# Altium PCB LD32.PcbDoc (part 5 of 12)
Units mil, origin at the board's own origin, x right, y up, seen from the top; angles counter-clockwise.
Board outline 7007.87 x 4368.85 mil, 12 copper layers (Top Layer, Int1 (GND), Int2 (AVDD), Int3 (DVDD), Int4 (GND), Int5 (ST), Int6 (SB), Int8 (AGND), Int7 (AVCC), Int9 (VCCA), Int10 (GND), Bottom Layer), stack 60.136 mil thick; 1165 components, 667 nets, 3910 pads, 2570 vias.
Unrouted connection lines stored in the file: 14.
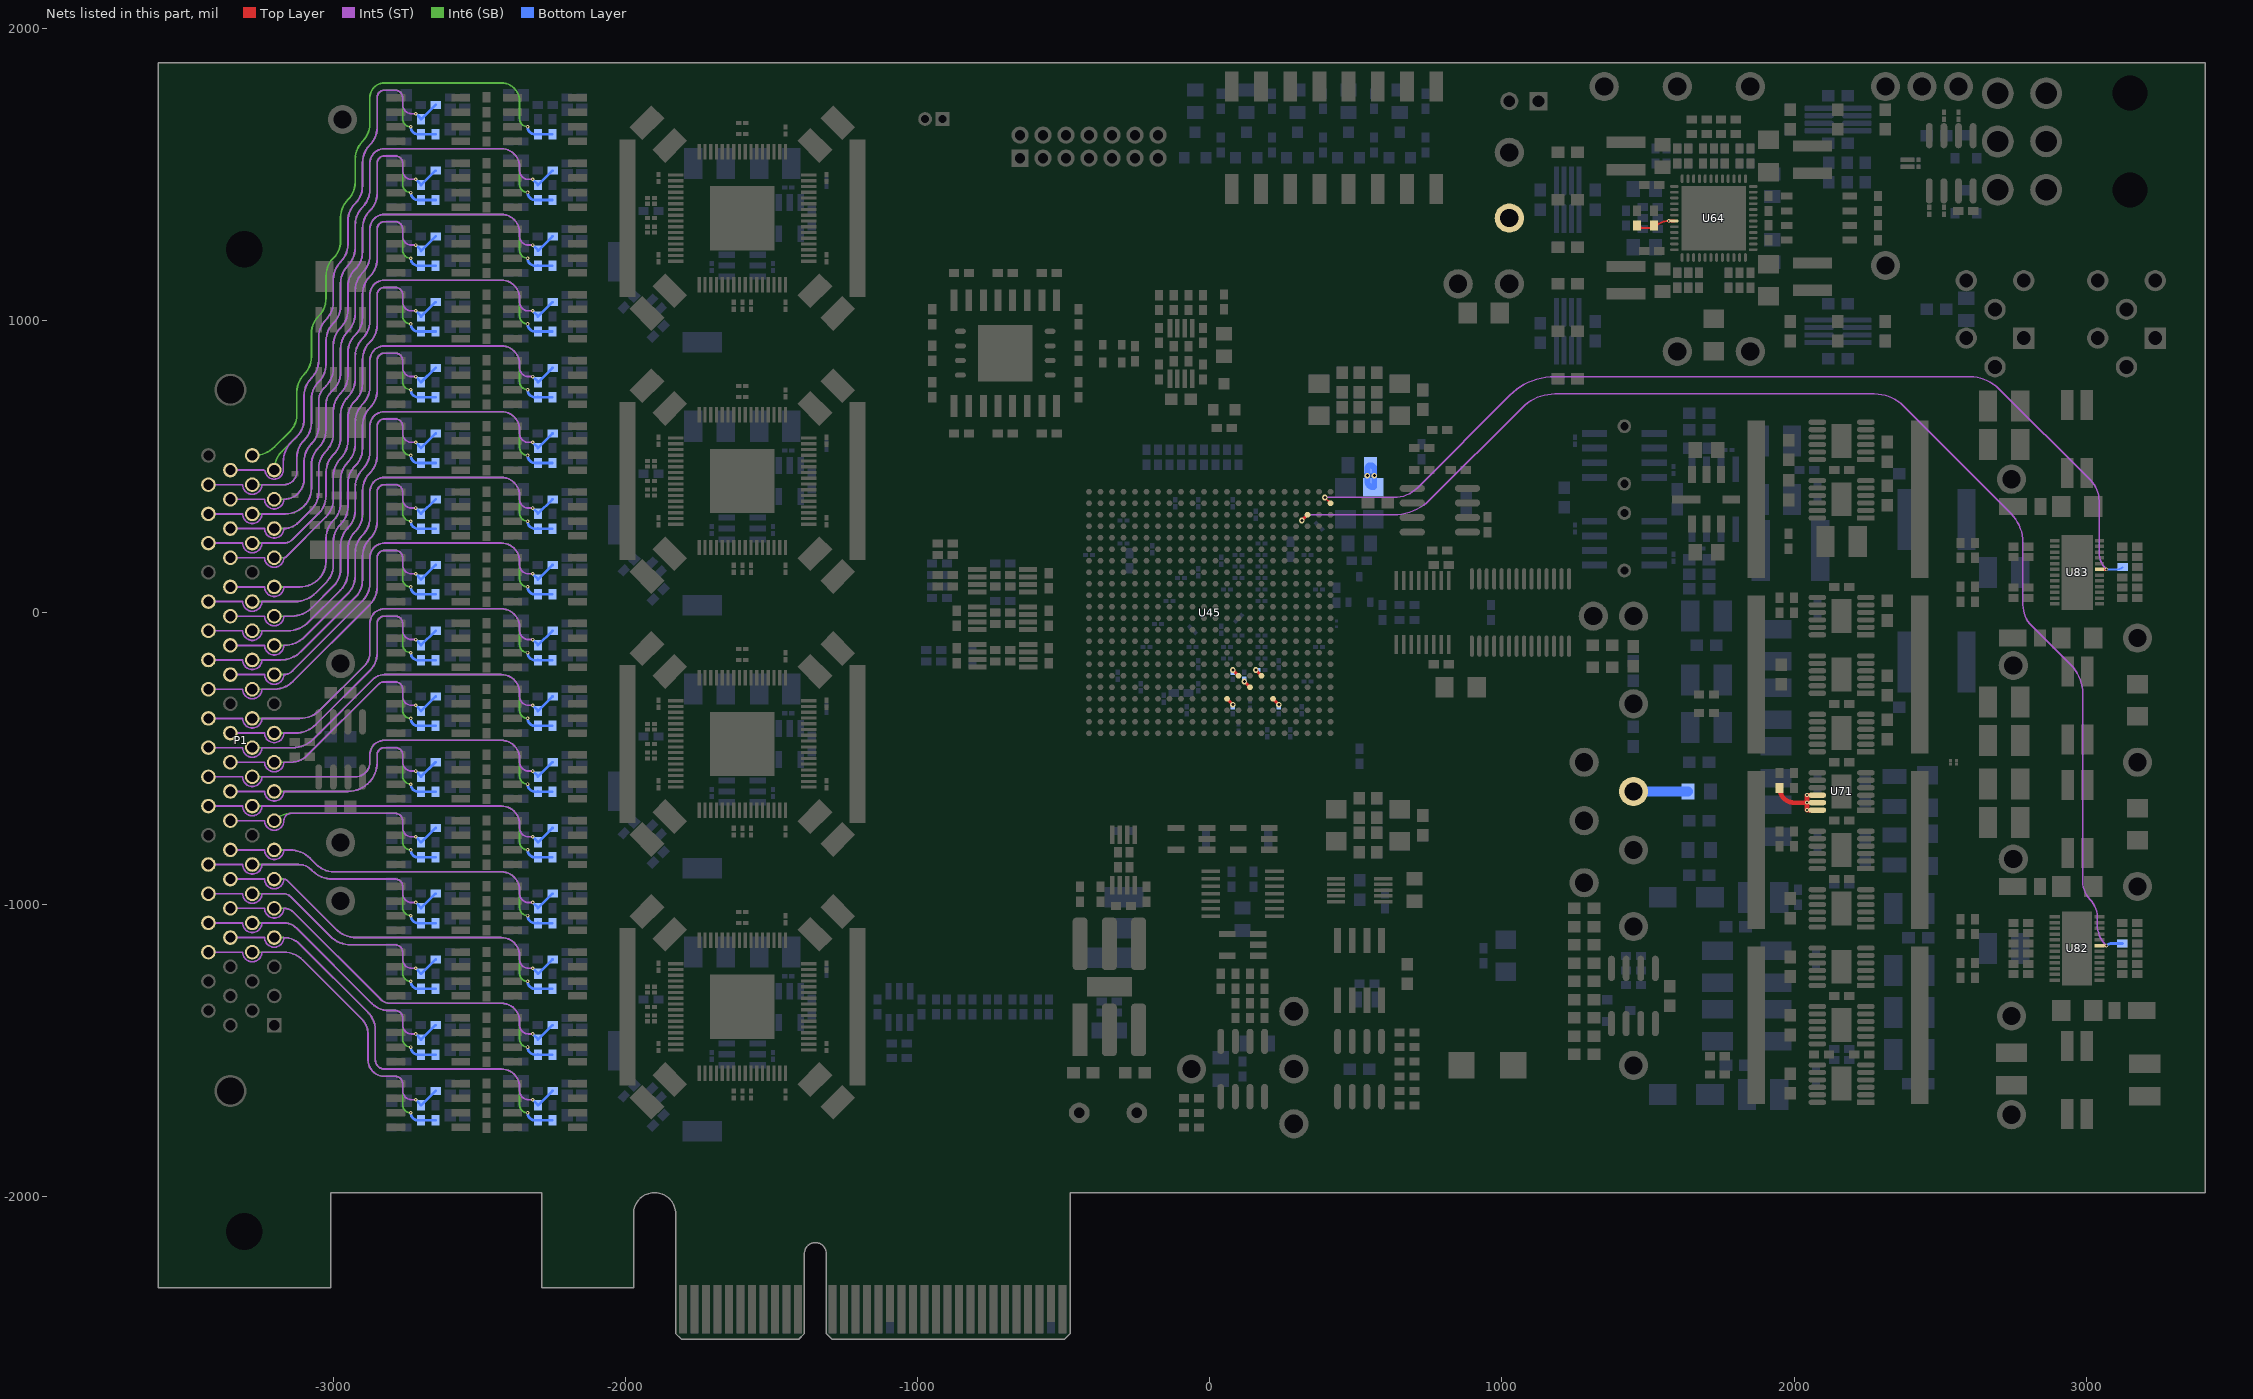
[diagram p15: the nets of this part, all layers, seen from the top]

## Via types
v1: diameter 12, hole 6, Top Layer to Bottom Layer, tented both sides, 1500 vias
v2: diameter 19, hole 10, Top Layer to Bottom Layer, tented both sides, 404 vias
v3: diameter 20, hole 10, Top Layer to Bottom Layer, tented both sides, 337 vias
v4: diameter 14, hole 7, Top Layer to Bottom Layer, tented both sides, 212 vias
v5: diameter 30, hole 15, Top Layer to Bottom Layer, tented both sides, 37 vias
v6: diameter 19.68, hole 7.87, Top Layer to Bottom Layer, 25 vias
v7: diameter 40, hole 20, Top Layer to Bottom Layer, tented both sides, 16 vias
v8: diameter 19.02, hole 10, Top Layer to Bottom Layer, tented both sides, 10 vias
v9: diameter 40, hole 20, Top Layer to Bottom Layer, 9 vias
v10: diameter 60, hole 40, Top Layer to Bottom Layer, 5 vias
v11: diameter 25, hole 13, Top Layer to Bottom Layer, 4 vias
v12: diameter 50, hole 25, Top Layer to Bottom Layer, tented both sides, 4 vias
v13: diameter 35, hole 20, Top Layer to Bottom Layer, 2 vias
v14: diameter 50, hole 25, Top Layer to Bottom Layer, 2 vias
v15: diameter 63, hole 45, Top Layer to Bottom Layer, 1 vias
v16: diameter 14.02, hole 7.01, Top Layer to Bottom Layer, tented both sides, 1 vias
v17: diameter 60, hole 40, Top Layer to Bottom Layer, tented both sides, 1 vias

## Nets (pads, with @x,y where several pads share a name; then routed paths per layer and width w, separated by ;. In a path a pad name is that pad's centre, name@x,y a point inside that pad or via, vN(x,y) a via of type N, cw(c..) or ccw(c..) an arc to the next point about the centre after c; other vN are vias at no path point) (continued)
ANALOG1.A1_P: C351C.2 P1.79 R367C.2 | length 2547
  Int6 (SB) w6: P1.79@-3277.3,537.5 -3272.05,537.5 ccw(c-3272.05,637.5) -3201.34,566.79 -3147.53,620.6 ccw(c-3201.93,675) -3125,675 -3125,754.29 cw(c-3039.64,754.29) -3100,814.64 ccw(c-3160.36,875) -3075,875 -3075,954.29 cw(c-2989.64,954.29) -3050,1014.64 ccw(c-3110.36,1075) -3025,1075 -3025,1152.14 cw(c-2939.64,1152.14) -3000,1212.5 ccw(c-3060.36,1272.86) -2975,1272.86 -2975,1352.14 cw(c-2889.64,1352.14) -2950,1412.5 ccw(c-3010.36,1472.86) -2925,1472.86 -2925,1552.14 cw(c-2839.64,1552.14) -2900,1612.5 ccw(c-2960.36,1672.86) -2875,1672.86 -2875,1762.5 cw(c-2825,1762.5) -2825,1812.5 -2425,1812.5 ; v1(-2335,1662.75) cw(c-2335,1690.25) -2362.5,1690.25 -2362.5,1750 ; -2425,1812.5 cw(c-2425,1750) -2362.5,1750 ; -2425,1812.5 cw(c-2425,1750) -2362.5,1750 ; -2425,1812.5 cw(c-2425,1750) -2362.5,1750 ; -2425,1812.5 cw(c-2425,1750) -2362.5,1750 ; -2425,1812.5 cw(c-2425,1750) -2362.5,1750
  Bottom Layer w9: v1(-2335,1662.75) ccw(c-2309.15,1662.75) -2309.15,1636.91 C351C.2@-2300,1636.91 ; C351C.2@-2300,1637.5 -2299.41,1636.91 R367C.2@-2250,1636.91
ANALOG1.A2_N: C351D.1 P1.68 R351D.2 | length 2391.9
  Int5 (ST) w6: P1.68@-3427.3,237.5 -3310.3,237.5 ccw(c-3277.3,237.5) -3244.3,237.5 -3169.3,237.5 ccw(c-3169.3,278.92) -3140.01,249.63 -3050,339.64 ccw(c-3110.36,400) -3025,400 -3025,479.29 cw(c-2939.64,479.29) -3000,539.64 ccw(c-3060.36,600) -2975,600 -2975,677.14 cw(c-2889.64,677.14) -2950,737.5 ccw(c-3010.36,797.86) -2925,797.86 -2925,877.14 cw(c-2839.64,877.14) -2900,937.5 ccw(c-2960.36,997.86) -2875,997.86 -2875,1087.5 cw(c-2825,1087.5) -2825,1137.5 -2425,1137.5 ; v1(-2317.5,1032.5) -2332.5,1032.5 cw(c-2332.5,1062.5) -2362.5,1062.5 -2362.5,1075 ; -2425,1137.5 cw(c-2425,1075) -2362.5,1075 ; -2425,1137.5 cw(c-2425,1075) -2362.5,1075 ; -2425,1137.5 cw(c-2425,1075) -2362.5,1075 ; -2425,1137.5 cw(c-2425,1075) -2362.5,1075 ; -2425,1137.5 cw(c-2425,1075) -2362.5,1075
  Bottom Layer w9: v1(-2317.5,1032.5) -2300,1015 C351D.1@-2300,1013.09 -2250.59,1062.5 R351D.2@-2249.41,1062.5
ANALOG1.A2_P: C351D.2 P1.67 R367D.2 | length 2234.8
  Int6 (SB) w6: P1.67@-3277.3,237.5 -3169.3,237.5 ccw(c-3169.3,278.92) -3140.01,249.63 -3050,339.64 ccw(c-3110.36,400) -3025,400 -3025,479.29 cw(c-2939.64,479.29) -3000,539.64 ccw(c-3060.36,600) -2975,600 -2975,677.14 cw(c-2889.64,677.14) -2950,737.5 ccw(c-3010.36,797.86) -2925,797.86 -2925,877.14 cw(c-2839.64,877.14) -2900,937.5 ccw(c-2960.36,997.86) -2875,997.86 -2875,1087.5 cw(c-2825,1087.5) -2825,1137.5 -2425,1137.5 ; v1(-2335,987.75) cw(c-2335,1015.25) -2362.5,1015.25 -2362.5,1075 ; -2425,1137.5 cw(c-2425,1075) -2362.5,1075 ; -2425,1137.5 cw(c-2425,1075) -2362.5,1075 ; -2425,1137.5 cw(c-2425,1075) -2362.5,1075 ; -2425,1137.5 cw(c-2425,1075) -2362.5,1075 ; -2425,1137.5 cw(c-2425,1075) -2362.5,1075
  Bottom Layer w9: v1(-2335,987.75) ccw(c-2309.15,987.75) -2309.15,961.91 C351D.2@-2300,961.91 ; C351D.2@-2300,962.5 -2299.41,961.91 R367D.2@-2250,961.91
ANALOG1.A3_N: C431C.1 P1.78 R415C.2 | length 1876.3
  Int5 (ST) w6: P1.78@-3352.3,487.5 -3238.78,487.5 cw(c-3238.81,481.5) -3232.9,482.5 ccw(c-3202.3,487.5) -3202.3,456.5 ccw(c-3202.3,487.5) -3171.3,487.5 -3171.3,514.42 cw(c-3071.3,514.42) -3142.01,585.13 -3125,602.14 ccw(c-3185.36,662.5) -3100,662.5 -3100,741.79 cw(c-3014.64,741.79) -3075,802.14 ccw(c-3135.36,862.5) -3050,862.5 -3050,941.79 cw(c-2964.64,941.79) -3025,1002.14 ccw(c-3085.36,1062.5) -3000,1062.5 -3000,1139.64 cw(c-2914.64,1139.64) -2975,1200 ccw(c-3035.36,1260.36) -2950,1260.36 -2950,1339.64 cw(c-2864.64,1339.64) -2925,1400 ccw(c-2985.36,1460.36) -2900,1460.36 -2900,1539.64 cw(c-2814.64,1539.64) -2875,1600 ccw(c-2935.36,1660.36) -2850,1660.36 -2850,1762.5 cw(c-2825,1762.5) -2825,1787.5 -2787.5,1787.5 cw(c-2787.5,1762.5) -2762.5,1762.5 -2762.5,1737.5 ccw(c-2732.5,1737.5) -2732.5,1707.5 v1(-2717.5,1707.5)
  Bottom Layer w9: v1(-2717.5,1707.5) C431C.1@-2700,1690 ; C431C.1@-2700,1688.09 R415C.2@-2649.41,1737.5
ANALOG1.A3_P: C431C.2 P1.77 R431C.2 | length 2133.2
  Int6 (SB) w6: P1.77@-3202.3,487.5 cw(c-3112.15,487.5) -3175.9,551.25 -3125,602.14 ccw(c-3185.36,662.5) -3100,662.5 -3100,741.79 cw(c-3014.64,741.79) -3075,802.14 ccw(c-3135.36,862.5) -3050,862.5 -3050,941.79 cw(c-2964.64,941.79) -3025,1002.14 ccw(c-3085.36,1062.5) -3000,1062.5 -3000,1139.64 cw(c-2914.64,1139.64) -2975,1200 ccw(c-3035.36,1260.36) -2950,1260.36 -2950,1339.64 cw(c-2864.64,1339.64) -2925,1400 ccw(c-2985.36,1460.36) -2900,1460.36 -2900,1539.64 cw(c-2814.64,1539.64) -2875,1600 ; v1(-2735,1662.5) cw(c-2735,1690) -2762.5,1690 -2762.5,1762.5 ccw(c-2787.5,1762.5) -2787.5,1787.5 -2825,1787.5 ; -2875,1600 ccw(c-2935.36,1660.36) -2850,1660.36 ; -2875,1600 ccw(c-2935.36,1660.36) -2850,1660.36 ; -2875,1600 ccw(c-2935.36,1660.36) -2850,1660.36 ; -2875,1600 ccw(c-2935.36,1660.36) -2850,1660.36 ; -2875,1600 ccw(c-2935.36,1660.36) -2850,1660.36 ; -2850,1660.36 -2850,1762.5 ; -2850,1762.5 cw(c-2825,1762.5) -2825,1787.5 ; -2850,1762.5 cw(c-2825,1762.5) -2825,1787.5 ; -2850,1762.5 cw(c-2825,1762.5) -2825,1787.5 ; -2850,1762.5 cw(c-2825,1762.5) -2825,1787.5 ; -2850,1762.5 cw(c-2825,1762.5) -2825,1787.5
  Bottom Layer w9: v1(-2735,1662.5) ccw(c-2709.41,1662.5) -2709.41,1636.91 C431C.2@-2700,1636.91 R431C.2@-2650,1636.91
ANALOG1.A4_N: C431D.1 P1.66 R415D.2 | length 1530.6
  Int5 (ST) w6: P1.66@-3352.3,187.5 -3235.3,187.5 ccw(c-3202.3,187.5) -3169.3,187.5 ccw(c-3169.3,198.74) -3161.35,190.79 -3025,327.14 ccw(c-3085.36,387.5) -3000,387.5 -3000,466.79 cw(c-2914.64,466.79) -2975,527.14 ccw(c-3035.36,587.5) -2950,587.5 -2950,664.64 cw(c-2864.64,664.64) -2925,725 ccw(c-2985.36,785.36) -2900,785.36 -2900,864.64 cw(c-2814.64,864.64) -2875,925 ccw(c-2935.36,985.36) -2850,985.36 -2850,1087.5 cw(c-2825,1087.5) -2825,1112.5 -2787.5,1112.5 cw(c-2787.5,1087.5) -2762.5,1087.5 -2762.5,1062.5 ccw(c-2732.5,1062.5) -2732.5,1032.5 v1(-2717.5,1032.5)
  Bottom Layer w9: v1(-2717.5,1032.5) -2700,1015 C431D.1@-2700,1013.09 ; C431D.1@-2700,1012.5 C431D.1@-2700,1013.09 ; R415D.2@-2649.41,1062.5 C431D.1@-2700,1013.09
ANALOG1.A4_P: C431D.2 P1.65 R431D.2 | length 1726.6
  Int6 (SB) w6: P1.65@-3202.3,187.5 -3169.3,187.5 ccw(c-3169.3,198.74) -3161.36,190.78 -3025,327.14 ccw(c-3085.36,387.5) -3000,387.5 -3000,466.79 cw(c-2914.64,466.79) -2975,527.14 ccw(c-3035.36,587.5) -2950,587.5 -2950,664.64 cw(c-2864.64,664.64) -2925,725 ccw(c-2985.36,785.36) -2900,785.36 -2900,864.64 cw(c-2814.64,864.64) -2875,925 ccw(c-2935.36,985.36) -2850,985.36 -2850,1087.5 ; v1(-2735,987.5) cw(c-2735,1015) -2762.5,1015 -2762.5,1087.5 ccw(c-2787.5,1087.5) -2787.5,1112.5 -2825,1112.5 ; -2850,1087.5 cw(c-2825,1087.5) -2825,1112.5 ; -2850,1087.5 cw(c-2825,1087.5) -2825,1112.5 ; -2850,1087.5 cw(c-2825,1087.5) -2825,1112.5 ; -2850,1087.5 cw(c-2825,1087.5) -2825,1112.5 ; -2850,1087.5 cw(c-2825,1087.5) -2825,1112.5 ; -2850,1087.5 cw(c-2825,1087.5) -2825,1112.5 ; -2850,1087.5 cw(c-2825,1087.5) -2825,1112.5 ; -2850,1087.5 cw(c-2825,1087.5) -2825,1112.5 ; -2850,1087.5 cw(c-2825,1087.5) -2825,1112.5 ; -2850,1087.5 cw(c-2825,1087.5) -2825,1112.5
  Bottom Layer w9: v1(-2735,987.5) ccw(c-2709.41,987.5) -2709.41,961.91 C431D.2@-2700,961.91 R431D.2@-2650,961.91
ANALOG1.A5_N: C351B.1 P1.76 R351B.2 | length 2236.8
  Int5 (ST) w6: P1.76@-3427.3,437.5 -3310.3,437.5 ccw(c-3277.3,437.5) -3244.3,437.5 -3169.3,437.5 ccw(c-3169.3,481.8) -3125,481.8 -3125,529.29 cw(c-3039.64,529.29) -3100,589.64 ccw(c-3160.36,650) -3075,650 -3075,729.29 cw(c-2989.64,729.29) -3050,789.64 ccw(c-3110.36,850) -3025,850 -3025,929.29 cw(c-2939.64,929.29) -3000,989.64 ccw(c-3060.36,1050) -2975,1050 -2975,1127.14 cw(c-2889.64,1127.14) -2950,1187.5 ccw(c-3010.36,1247.86) -2925,1247.86 -2925,1327.14 cw(c-2839.64,1327.14) -2900,1387.5 ccw(c-2960.36,1447.86) -2875,1447.86 -2875,1537.5 cw(c-2825,1537.5) -2825,1587.5 -2425,1587.5 cw(c-2425,1525) -2362.5,1525 -2362.5,1512.5 ccw(c-2332.5,1512.5) -2332.5,1482.5 v1(-2317.5,1482.5)
  Bottom Layer w9: v1(-2317.5,1482.5) -2300,1465 C351B.1@-2300,1463.09 -2250.59,1512.5 R351B.2@-2249.41,1512.5
ANALOG1.A5_P: C351B.2 P1.75 R367B.2 | length 2472.5
  Int6 (SB) w6: P1.75@-3277.3,437.5 -3169.3,437.5 ccw(c-3169.3,481.8) -3125,481.8 -3125,529.29 cw(c-3039.64,529.29) -3100,589.64 ccw(c-3160.36,650) -3075,650 -3075,729.29 cw(c-2989.64,729.29) -3050,789.64 ccw(c-3110.36,850) -3025,850 -3025,929.29 cw(c-2939.64,929.29) -3000,989.64 ccw(c-3060.36,1050) -2975,1050 -2975,1127.14 cw(c-2889.64,1127.14) -2950,1187.5 ccw(c-3010.36,1247.86) -2925,1247.86 -2925,1327.14 cw(c-2839.64,1327.14) -2900,1387.5 ccw(c-2960.36,1447.86) -2875,1447.86 -2875,1537.5 cw(c-2825,1537.5) -2825,1587.5 -2425,1587.5 ; v1(-2335,1437.75) cw(c-2335,1465.25) -2362.5,1465.25 -2362.5,1525 ; -2425,1587.5 cw(c-2425,1525) -2362.5,1525 ; -2425,1587.5 cw(c-2425,1525) -2362.5,1525 ; -2425,1587.5 cw(c-2425,1525) -2362.5,1525 ; -2425,1587.5 cw(c-2425,1525) -2362.5,1525 ; -2425,1587.5 cw(c-2425,1525) -2362.5,1525
  Bottom Layer w9: v1(-2335,1437.75) ccw(c-2309.15,1437.75) -2309.15,1411.91 C351B.2@-2300,1411.91 ; C351B.2@-2300,1412.5 -2299.41,1411.91 R367B.2@-2250,1411.91
ANALOG1.A6_N: C351A.1 P1.72 R351A.2 | length 2523.1
  Int5 (ST) w6: P1.72@-3427.3,337.5 -3310.3,337.5 ccw(c-3277.3,337.5) -3244.3,337.5 -3165.53,337.5 ccw(c-3165.53,430.18) -3100,364.64 ccw(c-3160.36,425) -3075,425 -3075,504.29 cw(c-2989.64,504.29) -3050,564.64 ccw(c-3110.36,625) -3025,625 -3025,712.5 cw(c-2964.64,712.5) -3007.32,755.18 -3000,762.5 ccw(c-3060.36,822.86) -2975,822.86 -2975,902.14 cw(c-2889.64,902.14) -2950,962.5 ccw(c-3010.36,1022.86) -2925,1022.86 -2925,1102.14 cw(c-2839.64,1102.14) -2900,1162.5 ccw(c-2960.36,1222.86) -2875,1222.86 -2875,1312.5 cw(c-2825,1312.5) -2825,1362.5 -2425,1362.5 ; v1(-2317.5,1257.5) -2332.5,1257.5 cw(c-2332.5,1287.5) -2362.5,1287.5 -2362.5,1300 ; -2425,1362.5 cw(c-2425,1300) -2362.5,1300 ; -2425,1362.5 cw(c-2425,1300) -2362.5,1300 ; -2425,1362.5 cw(c-2425,1300) -2362.5,1300 ; -2425,1362.5 cw(c-2425,1300) -2362.5,1300 ; -2425,1362.5 cw(c-2425,1300) -2362.5,1300
  Bottom Layer w9: v1(-2317.5,1257.5) -2300,1240 C351A.1@-2300,1238.09 -2250.59,1287.5 R351A.2@-2249.41,1287.5
ANALOG1.A6_P: C351A.2 P1.71 R367A.2 | length 2366.6
  Int6 (SB) w6: P1.71@-3277.3,337.5 -3162.5,337.5 ccw(c-3162.5,425) -3075,425 -3075,504.29 cw(c-2989.64,504.29) -3050,564.64 ccw(c-3110.36,625) -3025,625 -3025,712.5 cw(c-2964.64,712.5) -3007.32,755.18 -3000,762.5 ccw(c-3060.36,822.86) -2975,822.86 -2975,902.14 cw(c-2889.64,902.14) -2950,962.5 ccw(c-3010.36,1022.86) -2925,1022.86 -2925,1102.14 cw(c-2839.64,1102.14) -2900,1162.5 ccw(c-2960.36,1222.86) -2875,1222.86 -2875,1312.5 cw(c-2825,1312.5) -2825,1362.5 -2425,1362.5 ; v1(-2335,1212.75) cw(c-2335,1240.25) -2362.5,1240.25 -2362.5,1300 ; -2425,1362.5 cw(c-2425,1300) -2362.5,1300 ; -2425,1362.5 cw(c-2425,1300) -2362.5,1300 ; -2425,1362.5 cw(c-2425,1300) -2362.5,1300 ; -2425,1362.5 cw(c-2425,1300) -2362.5,1300 ; -2425,1362.5 cw(c-2425,1300) -2362.5,1300
  Bottom Layer w9: v1(-2335,1212.75) ccw(c-2309.15,1212.75) -2309.15,1186.91 C351A.2@-2300,1186.91 ; C351A.2@-2300,1187.5 -2299.41,1186.91 R367A.2@-2250,1186.91
ANALOG1.A7_N: C431B.1 P1.74 R415B.2 | length 1779.3
  Int5 (ST) w6: P1.74@-3352.3,387.5 -3235.3,387.5 ccw(c-3202.3,387.5) -3169.3,387.5 ccw(c-3169.3,456.8) -3100,456.8 -3100,516.79 cw(c-3014.64,516.79) -3075,577.14 ccw(c-3135.36,637.5) -3050,637.5 -3050,725 cw(c-2989.64,725) -3032.32,767.68 -3025,775 ccw(c-3085.36,835.36) -3000,835.36 -3000,914.64 cw(c-2914.64,914.64) -2975,975 ccw(c-3035.36,1035.36) -2950,1035.36 -2950,1114.64 cw(c-2864.64,1114.64) -2925,1175 ccw(c-2985.36,1235.36) -2900,1235.36 -2900,1314.64 cw(c-2814.64,1314.64) -2875,1375 ccw(c-2935.36,1435.36) -2850,1435.36 -2850,1537.5 cw(c-2825,1537.5) -2825,1562.5 -2787.5,1562.5 cw(c-2787.5,1537.5) -2762.5,1537.5 -2762.5,1512.5 ccw(c-2732.5,1512.5) -2732.5,1482.5 v1(-2717.5,1482.5)
  Bottom Layer w9: v1(-2717.5,1482.5) -2700,1465 C431B.1@-2700,1463.09 ; C431B.1@-2700,1462.5 C431B.1@-2700,1463.09 ; R415B.2@-2649.41,1512.5 C431B.1@-2700,1463.09
ANALOG1.A7_P: C431B.2 P1.73 R431B.2 | length 2047
  Int6 (SB) w6: P1.73@-3202.3,387.5 -3169.3,387.5 ccw(c-3169.3,456.8) -3100,456.8 -3100,516.79 cw(c-3014.64,516.79) -3075,577.14 ccw(c-3135.36,637.5) -3050,637.5 -3050,725 cw(c-2989.64,725) -3032.32,767.68 -3025,775 ccw(c-3085.36,835.36) -3000,835.36 -3000,914.64 cw(c-2914.64,914.64) -2975,975 ccw(c-3035.36,1035.36) -2950,1035.36 -2950,1114.64 cw(c-2864.64,1114.64) -2925,1175 ccw(c-2985.36,1235.36) -2900,1235.36 -2900,1314.64 cw(c-2814.64,1314.64) -2875,1375 ; v1(-2735,1437.5) cw(c-2735,1465) -2762.5,1465 -2762.5,1537.5 ccw(c-2787.5,1537.5) -2787.5,1562.5 -2825,1562.5 ; -2875,1375 ccw(c-2935.36,1435.36) -2850,1435.36 ; -2875,1375 ccw(c-2935.36,1435.36) -2850,1435.36 ; -2875,1375 ccw(c-2935.36,1435.36) -2850,1435.36 ; -2875,1375 ccw(c-2935.36,1435.36) -2850,1435.36 ; -2875,1375 ccw(c-2935.36,1435.36) -2850,1435.36 ; -2850,1435.36 -2850,1537.5 ; -2850,1537.5 cw(c-2825,1537.5) -2825,1562.5 ; -2850,1537.5 cw(c-2825,1537.5) -2825,1562.5 ; -2850,1537.5 cw(c-2825,1537.5) -2825,1562.5 ; -2850,1537.5 cw(c-2825,1537.5) -2825,1562.5 ; -2850,1537.5 cw(c-2825,1537.5) -2825,1562.5
  Bottom Layer w9: v1(-2735,1437.5) ccw(c-2709.41,1437.5) -2709.41,1411.91 C431B.2@-2700,1411.91 R431B.2@-2650,1411.91
ANALOG1.A8_N: C431A.1 P1.70 R415A.2 | length 1660.3
  Int5 (ST) w6: P1.70@-3352.3,287.5 -3235.3,287.5 ccw(c-3202.3,287.5) -3169.3,287.5 ccw(c-3169.3,359.1) -3118.67,308.47 -3075,352.14 ccw(c-3135.36,412.5) -3050,412.5 -3050,491.79 cw(c-2964.64,491.79) -3025,552.14 ccw(c-3085.36,612.5) -3000,612.5 -3000,689.64 cw(c-2914.64,689.64) -2975,750 ccw(c-3035.36,810.36) -2950,810.36 -2950,889.64 cw(c-2864.64,889.64) -2925,950 ccw(c-2985.36,1010.36) -2900,1010.36 -2900,1089.64 cw(c-2814.64,1089.64) -2875,1150 ccw(c-2935.36,1210.36) -2850,1210.36 -2850,1312.5 cw(c-2825,1312.5) -2825,1337.5 -2787.5,1337.5 cw(c-2787.5,1312.5) -2762.5,1312.5 -2762.5,1287.5 ccw(c-2732.5,1287.5) -2732.5,1257.5 v1(-2717.5,1257.5)
  Bottom Layer w9: v1(-2717.5,1257.5) -2700,1240 C431A.1@-2700,1238.09 ; C431A.1@-2700,1237.5 C431A.1@-2700,1238.09 ; R415A.2@-2649.41,1287.5 C431A.1@-2700,1238.09
ANALOG1.A8_P: C431A.2 P1.69 R431A.2 | length 1659.9
  Int6 (SB) w6: P1.69@-3202.3,287.5 -3169.3,287.5 ccw(c-3169.3,359.1) -3118.67,308.47 -3075,352.14 ccw(c-3135.36,412.5) -3050,412.5 -3050,491.79 cw(c-2964.64,491.79) -3025,552.14 ccw(c-3085.36,612.5) -3000,612.5 -3000,689.64 cw(c-2914.64,689.64) -2975,750 ccw(c-3035.36,810.36) -2950,810.36 -2950,889.64 cw(c-2864.64,889.64) -2925,950 ccw(c-2985.36,1010.36) -2900,1010.36 -2900,1089.64 cw(c-2814.64,1089.64) -2875,1150 ccw(c-2935.36,1210.36) -2850,1210.36 -2850,1312.5 ; v1(-2735,1212.5) cw(c-2735,1240) -2762.5,1240 -2762.5,1312.5 ccw(c-2787.5,1312.5) -2787.5,1337.5 -2825,1337.5 ; -2850,1312.5 cw(c-2825,1312.5) -2825,1337.5 ; -2850,1312.5 cw(c-2825,1312.5) -2825,1337.5 ; -2850,1312.5 cw(c-2825,1312.5) -2825,1337.5 ; -2850,1312.5 cw(c-2825,1312.5) -2825,1337.5 ; -2850,1312.5 cw(c-2825,1312.5) -2825,1337.5
  Bottom Layer w9: v1(-2735,1212.5) ccw(c-2709.41,1212.5) -2709.41,1186.91 C431A.2@-2700,1186.91 R431A.2@-2650,1186.91
ANALOG2.A1_N: C351G.1 P1.62 R351G.2 | length 2283.6
  Int5 (ST) w6: P1.62@-3352.3,87.5 -3235.3,87.5 ccw(c-3202.3,87.5) -3169.3,87.5 -3115.53,87.5 ccw(c-3115.53,180.18) -3050,114.64 ccw(c-3110.36,175) -3025,175 -3025,254.29 cw(c-2939.64,254.29) -3000,314.64 ccw(c-3060.36,375) -2975,375 -2975,454.29 cw(c-2889.64,454.29) -2950,514.64 ccw(c-3010.36,575) -2925,575 -2925,652.14 cw(c-2839.64,652.14) -2900,712.5 ccw(c-2960.36,772.86) -2875,772.86 -2875,862.5 cw(c-2825,862.5) -2825,912.5 -2425,912.5 ; v1(-2317.5,807.5) -2332.5,807.5 cw(c-2332.5,837.5) -2362.5,837.5 -2362.5,850 ; -2425,912.5 cw(c-2425,850) -2362.5,850 ; -2425,912.5 cw(c-2425,850) -2362.5,850 ; -2425,912.5 cw(c-2425,850) -2362.5,850 ; -2425,912.5 cw(c-2425,850) -2362.5,850 ; -2425,912.5 cw(c-2425,850) -2362.5,850
  Bottom Layer w9: v1(-2317.5,807.5) -2300,790 C351G.1@-2300,788.09 -2250.59,837.5 R351G.2@-2249.41,837.5
ANALOG2.A1_P: C351G.2 P1.61 R367G.2 | length 2126.8
  Int6 (SB) w6: P1.61@-3202.3,87.5 -3115.53,87.5 ccw(c-3115.53,180.18) -3050,114.64 ccw(c-3110.35,175) -3025,175 -3025,254.29 cw(c-2939.64,254.29) -3000,314.64 -2998.48,316.16 ccw(c-3055.18,372.86) -2975,372.86 -2975,454.29 cw(c-2889.64,454.29) -2950,514.64 ccw(c-3010.36,575) -2925,575 -2925,652.14 cw(c-2839.64,652.14) -2900,712.5 ccw(c-2960.36,772.86) -2875,772.86 -2875,862.5 cw(c-2825,862.5) -2825,912.5 -2425,912.5 ; v1(-2335,762.75) cw(c-2335,790.25) -2362.5,790.25 -2362.5,850 ; -2425,912.5 cw(c-2425,850) -2362.5,850 ; -2425,912.5 cw(c-2425,850) -2362.5,850 ; -2425,912.5 cw(c-2425,850) -2362.5,850 ; -2425,912.5 cw(c-2425,850) -2362.5,850 ; -2425,912.5 cw(c-2425,850) -2362.5,850
  Bottom Layer w9: v1(-2335,762.75) ccw(c-2309.15,762.75) -2309.15,736.91 C351G.2@-2300,736.91 ; C351G.2@-2300,737.5 -2299.41,736.91 R367G.2@-2250,736.91
ANALOG2.A2_N: C351H.1 P1.50 R351H.2 | length 1888.9
  Int5 (ST) w6: P1.50@-3352.3,-212.5 -3235.3,-212.5 ccw(c-3202.3,-212.5) -3169.3,-212.5 ccw(c-3169.3,-171.08) -3140.01,-200.37 -2900,39.64 ccw(c-2960.36,100) -2875,100 -2875,187.5 cw(c-2825,187.5) -2825,237.5 -2425,237.5 ; v1(-2317.5,132.5) -2332.5,132.5 cw(c-2332.5,162.5) -2362.5,162.5 -2362.5,175 ; -2425,237.5 cw(c-2425,175) -2362.5,175 ; -2425,237.5 cw(c-2425,175) -2362.5,175 ; -2425,237.5 cw(c-2425,175) -2362.5,175 ; -2425,237.5 cw(c-2425,175) -2362.5,175 ; -2425,237.5 cw(c-2425,175) -2362.5,175
  Bottom Layer w9: v1(-2317.5,132.5) -2300,115 C351H.1@-2300,113.09 -2250.59,162.5 R351H.2@-2249.41,162.5
ANALOG2.A2_P: C351H.2 P1.49 R367H.2 | length 1731.9
  Int6 (SB) w6: P1.49@-3202.3,-212.5 -3169.3,-212.5 ccw(c-3169.3,-171.08) -3140.01,-200.37 -2900,39.64 ccw(c-2960.36,100) -2875,100 -2875,187.5 cw(c-2825,187.5) -2825,237.5 -2425,237.5 ; v1(-2335,87.75) cw(c-2335,115.25) -2362.5,115.25 -2362.5,175 ; -2425,237.5 cw(c-2425,175) -2362.5,175 ; -2425,237.5 cw(c-2425,175) -2362.5,175 ; -2425,237.5 cw(c-2425,175) -2362.5,175 ; -2425,237.5 cw(c-2425,175) -2362.5,175 ; -2425,237.5 cw(c-2425,175) -2362.5,175
  Bottom Layer w9: v1(-2335,87.75) ccw(c-2309.15,87.75) -2309.15,61.91 C351H.2@-2300,61.91 ; C351H.2@-2300,62.5 -2299.41,61.91 R367H.2@-2250,61.91
ANALOG2.A3_N: C431G.1 P1.60 R415G.2 | length 1569.6
  Int5 (ST) w6: P1.60@-3427.3,37.5 -3310.3,37.5 ccw(c-3277.3,37.5) -3244.3,37.5 -3131.07,37.5 ccw(c-3131.07,137.5) -3060.36,66.79 -3025,102.14 ccw(c-3085.36,162.5) -3000,162.5 -3000,241.79 cw(c-2914.64,241.79) -2975,302.14 ccw(c-3035.36,362.5) -2950,362.5 -2950,441.79 cw(c-2864.64,441.79) -2925,502.14 ccw(c-2985.36,562.5) -2900,562.5 -2900,639.64 cw(c-2814.64,639.64) -2875,700 ccw(c-2935.36,760.36) -2850,760.36 -2850,862.5 cw(c-2825,862.5) -2825,887.5 -2787.5,887.5 cw(c-2787.5,862.5) -2762.5,862.5 -2762.5,837.5 ccw(c-2732.5,837.5) -2732.5,807.5 v1(-2717.5,807.5)
  Bottom Layer w9: v1(-2717.5,807.5) C431G.1@-2700,788.09 R415G.2@-2649.41,837.5
ANALOG2.A3_P: C431G.2 P1.59 R431G.2 | length 1766.9
  Int6 (SB) w6: P1.59@-3277.3,37.5 -3131.07,37.5 ccw(c-3131.07,137.5) -3060.36,66.79 -3025,102.14 ccw(c-3085.36,162.5) -3000,162.5 -3000,241.79 cw(c-2914.64,241.79) -2975,302.14 -2973.48,303.66 ccw(c-3030.18,360.36) -2950,360.36 -2950,441.79 cw(c-2864.64,441.79) -2925,502.14 ccw(c-2985.36,562.5) -2900,562.5 -2900,639.64 cw(c-2814.64,639.64) -2875,700 ccw(c-2935.36,760.36) -2850,760.36 -2850,862.5 ; v1(-2735,762.5) cw(c-2735,790) -2762.5,790 -2762.5,862.5 ccw(c-2787.5,862.5) -2787.5,887.5 -2825,887.5 ; -2850,862.5 cw(c-2825,862.5) -2825,887.5 ; -2850,862.5 cw(c-2825,862.5) -2825,887.5 ; -2850,862.5 cw(c-2825,862.5) -2825,887.5 ; -2850,862.5 cw(c-2825,862.5) -2825,887.5 ; -2850,862.5 cw(c-2825,862.5) -2825,887.5 ; -2850,862.5 cw(c-2825,862.5) -2825,887.5 ; -2850,862.5 cw(c-2825,862.5) -2825,887.5 ; -2850,862.5 cw(c-2825,862.5) -2825,887.5 ; -2850,862.5 cw(c-2825,862.5) -2825,887.5 ; -2850,862.5 cw(c-2825,862.5) -2825,887.5
  Bottom Layer w9: v1(-2735,762.5) ccw(c-2709.41,762.5) -2709.41,736.91 C431G.2@-2700,736.91 R431G.2@-2650,736.91
ANALOG2.A4_N: C431H.1 P1.48 R415H.2 | length 1173.1
  Int5 (ST) w6: P1.48@-3427.3,-262.5 -3310.3,-262.5 ccw(c-3277.3,-262.5) -3244.3,-262.5 -3202.3,-262.5 ccw(c-3202.3,-171.59) -3138.02,-235.87 -2875,27.14 ccw(c-2935.36,87.5) -2850,87.5 -2850,187.5 cw(c-2825,187.5) -2825,212.5 -2787.5,212.5 cw(c-2787.5,187.5) -2762.5,187.5 -2762.5,162.5 ccw(c-2732.5,162.5) -2732.5,132.5 v1(-2717.5,132.5)
  Bottom Layer w9: v1(-2717.5,132.5) C431H.1@-2700,113.09 R415H.2@-2649.41,162.5
ANALOG2.A4_P: C431H.2 P1.47 R431H.2 | length 1016.7
  Int6 (SB) w6: P1.47@-3277.3,-262.5 -3202.3,-262.5 ccw(c-3202.3,-171.59) -3138.02,-235.87 -2875,27.14 ccw(c-2935.36,87.5) -2850,87.5 -2850,187.5 cw(c-2825,187.5) -2825,212.5 -2787.5,212.5 cw(c-2787.5,187.5) -2762.5,187.5 -2762.5,115 ccw(c-2735,115) v1(-2735,87.5)
  Bottom Layer w9: v1(-2735,87.5) ccw(c-2709.41,87.5) -2709.41,61.91 C431H.2@-2700,61.91 R431H.2@-2650,61.91
ANALOG2.A5_N: C351F.1 P1.58 R351F.2 | length 2151
  Int5 (ST) w6: P1.58@-3352.3,-12.5 -3235.3,-12.5 ccw(c-3202.3,-12.5) -3169.3,-12.5 -3143.57,-12.5 ccw(c-3143.57,87.5) -3072.86,16.79 -3000,89.64 ccw(c-3060.36,150) -2975,150 -2975,229.29 cw(c-2889.64,229.29) -2950,289.64 ccw(c-3010.36,350) -2925,350 -2925,429.29 cw(c-2839.64,429.29) -2900,489.64 ccw(c-2960.36,550) -2875,550 -2875,637.5 cw(c-2825,637.5) -2825,687.5 -2425,687.5 ; v1(-2317.5,582.5) -2332.5,582.5 cw(c-2332.5,612.5) -2362.5,612.5 -2362.5,625 ; -2425,687.5 cw(c-2425,625) -2362.5,625 ; -2425,687.5 cw(c-2425,625) -2362.5,625 ; -2425,687.5 cw(c-2425,625) -2362.5,625 ; -2425,687.5 cw(c-2425,625) -2362.5,625 ; -2425,687.5 cw(c-2425,625) -2362.5,625
  Bottom Layer w9: v1(-2317.5,582.5) -2300,565 C351F.1@-2300,563.09 -2250.59,612.5 R351F.2@-2249.41,612.5
ANALOG2.A5_P: C351F.2 P1.57 R367F.2 | length 1601.5
  Int6 (SB) w6: P1.57@-3202.3,-12.5 -3143.57,-12.5 ccw(c-3143.57,87.5) -3072.86,16.79 -3000,89.64 ccw(c-3060.36,150) -2975,150 -2975,229.29 cw(c-2889.64,229.29) -2950,289.64 -2948.48,291.16 ccw(c-3005.18,347.86) -2925,347.86 -2925,429.29 cw(c-2839.64,429.29) -2900,489.64 ccw(c-2960.36,550) -2875,550 -2875,637.5 cw(c-2825,637.5) -2825,687.5 -2425,687.5 cw(c-2425,625) -2362.5,625 -2362.5,565.25 ccw(c-2335,565.25) v1(-2335,537.75)
  Bottom Layer w9: v1(-2335,537.75) ccw(c-2309.15,537.75) -2309.15,511.91 C351F.2@-2300,511.91 ; C351F.2@-2300,512.5 -2299.41,511.91 R367F.2@-2250,511.91
ANALOG2.A6_N: C351E.1 P1.54 R351E.2 | length 2018.7
  Int5 (ST) w6: P1.54@-3352.3,-112.5 -3235.3,-112.5 ccw(c-3202.3,-112.5) -3169.3,-112.5 -3168.57,-112.5 ccw(c-3168.57,-12.5) -3097.86,-83.21 -2950,64.64 ccw(c-3010.36,125) -2925,125 -2925,204.29 cw(c-2839.64,204.29) -2900,264.64 ccw(c-2960.36,325) -2875,325 -2875,412.5 cw(c-2825,412.5) -2825,462.5 -2425,462.5 ; v1(-2317.5,357.5) -2332.5,357.5 cw(c-2332.5,387.5) -2362.5,387.5 -2362.5,400 ; -2425,462.5 cw(c-2425,400) -2362.5,400 ; -2425,462.5 cw(c-2425,400) -2362.5,400 ; -2425,462.5 cw(c-2425,400) -2362.5,400 ; -2425,462.5 cw(c-2425,400) -2362.5,400 ; -2425,462.5 cw(c-2425,400) -2362.5,400
  Bottom Layer w9: v1(-2317.5,357.5) -2300,340 C351E.1@-2300,338.09 -2250.59,387.5 R351E.2@-2249.41,387.5
ANALOG2.A6_P: C351E.2 P1.53 R367E.2 | length 1861.9
  Int6 (SB) w6: P1.53@-3202.3,-112.5 -3168.57,-112.5 ccw(c-3168.57,-12.5) -3097.86,-83.21 -2950,64.64 ccw(c-3010.36,125) -2925,125 -2925,204.29 cw(c-2839.64,204.29) -2900,264.64 -2898.48,266.16 ccw(c-2955.18,322.86) -2875,322.86 -2875,412.5 cw(c-2825,412.5) -2825,462.5 -2425,462.5 ; v1(-2335,312.75) cw(c-2335,340.25) -2362.5,340.25 -2362.5,400 ; -2425,462.5 cw(c-2425,400) -2362.5,400 ; -2425,462.5 cw(c-2425,400) -2362.5,400 ; -2425,462.5 cw(c-2425,400) -2362.5,400 ; -2425,462.5 cw(c-2425,400) -2362.5,400 ; -2425,462.5 cw(c-2425,400) -2362.5,400
  Bottom Layer w9: v1(-2335,312.75) ccw(c-2309.15,312.75) -2309.15,286.91 C351E.2@-2300,286.91 ; C351E.2@-2300,287.5 -2299.41,286.91 R367E.2@-2250,286.91
ANALOG2.A7_N: C431F.1 P1.56 R415F.2 | length 1437.3
  Int5 (ST) w6: P1.56@-3427.3,-62.5 -3310.3,-62.5 ccw(c-3277.3,-62.5) -3244.3,-62.5 -3156.07,-62.5 ccw(c-3156.07,37.5) -3085.36,-33.21 -2975,77.14 ccw(c-3035.36,137.5) -2950,137.5 -2950,216.79 cw(c-2864.64,216.79) -2925,277.14 ccw(c-2985.36,337.5) -2900,337.5 -2900,416.79 cw(c-2814.64,416.79) -2875,477.14 ccw(c-2935.36,537.5) -2850,537.5 -2850,637.5 cw(c-2825,637.5) -2825,662.5 -2787.5,662.5 cw(c-2787.5,637.5) -2762.5,637.5 -2762.5,612.5 ccw(c-2732.5,612.5) -2732.5,582.5 v1(-2717.5,582.5)
  Bottom Layer w9: v1(-2717.5,582.5) C431F.1@-2700,563.09 R415F.2@-2649.41,612.5
ANALOG2.A7_P: C431F.2 P1.55 R431F.2 | length 1281.2
  Int6 (SB) w6: P1.55@-3277.3,-62.5 -3156.07,-62.5 ccw(c-3156.07,37.5) -3085.36,-33.21 -2975,77.14 ccw(c-3035.36,137.5) -2950,137.5 -2950,216.79 cw(c-2864.64,216.79) -2925,277.14 -2923.48,278.66 ccw(c-2980.18,335.36) -2900,335.36 -2900,416.79 cw(c-2814.64,416.79) -2875,477.14 ccw(c-2935.36,537.5) -2850,537.5 -2850,637.5 cw(c-2825,637.5) -2825,662.5 -2787.5,662.5 cw(c-2787.5,637.5) -2762.5,637.5 -2762.5,565 ccw(c-2735,565) v1(-2735,537.5)
  Bottom Layer w9: v1(-2735,537.5) ccw(c-2709.41,537.5) -2709.41,511.91 C431F.2@-2700,511.91 R431F.2@-2650,511.91
ANALOG2.A8_N: C431E.1 P1.52 R415E.2 | length 1305
  Int5 (ST) w6: P1.52@-3427.3,-162.5 -3310.3,-162.5 ccw(c-3277.3,-162.5) -3244.3,-162.5 -3181.07,-162.5 ccw(c-3181.07,-62.5) -3110.36,-133.21 -2925,52.14 ccw(c-2985.36,112.5) -2900,112.5 -2900,191.79 cw(c-2814.64,191.79) -2875,252.14 ccw(c-2935.36,312.5) -2850,312.5 -2850,412.5 cw(c-2825,412.5) -2825,437.5 -2787.5,437.5 cw(c-2787.5,412.5) -2762.5,412.5 -2762.5,387.5 ccw(c-2732.5,387.5) -2732.5,357.5 v1(-2717.5,357.5)
  Bottom Layer w9: v1(-2717.5,357.5) C431E.1@-2700,338.09 R415E.2@-2649.41,387.5
ANALOG2.A8_P: C431E.2 P1.51 R431E.2 | length 1148.9
  Int6 (SB) w6: P1.51@-3277.3,-162.5 -3181.07,-162.5 ccw(c-3181.07,-62.5) -3110.36,-133.21 -2925,52.14 ccw(c-2985.36,112.5) -2900,112.5 -2900,191.79 cw(c-2814.64,191.79) -2875,252.14 -2873.48,253.66 ccw(c-2930.18,310.36) -2850,310.36 -2850,412.5 cw(c-2825,412.5) -2825,437.5 -2787.5,437.5 cw(c-2787.5,412.5) -2762.5,412.5 -2762.5,340 ccw(c-2735,340) v1(-2735,312.5)
  Bottom Layer w9: v1(-2735,312.5) ccw(c-2709.41,312.5) -2709.41,286.91 C431E.2@-2700,286.91 R431E.2@-2650,286.91
ANALOG3.A1_N: C351K.1 P1.44 R351K.2 | length 1933.3
  Int5 (ST) w6: P1.44@-3427.3,-362.5 -3310.3,-362.5 ccw(c-3277.3,-362.5) -3244.3,-362.5 -3115.35,-362.5 ccw(c-3115.35,-262.5) -3044.64,-333.21 -2892.79,-181.37 ccw(c-2935.75,-138.41) -2875,-138.41 -2875,-37.5 cw(c-2825,-37.5) -2825,12.5 -2425,12.5 ; v1(-2317.5,-92.5) -2332.5,-92.5 cw(c-2332.5,-62.5) -2362.5,-62.5 -2362.5,-50 ; -2425,12.5 cw(c-2425,-50) -2362.5,-50 ; -2425,12.5 cw(c-2425,-50) -2362.5,-50 ; -2425,12.5 cw(c-2425,-50) -2362.5,-50 ; -2425,12.5 cw(c-2425,-50) -2362.5,-50 ; -2425,12.5 cw(c-2425,-50) -2362.5,-50
  Bottom Layer w9: v1(-2317.5,-92.5) -2300,-110 C351K.1@-2300,-111.91 -2250.59,-62.5 R351K.2@-2249.41,-62.5
ANALOG3.A1_P: C351K.2 P1.43 R367K.2 | length 1775.1
  Int6 (SB) w6: P1.43@-3276.23,-362.5 -3115.35,-362.5 ccw(c-3115.35,-262.5) -3044.64,-333.21 -2892.79,-181.37 ccw(c-2935.75,-138.41) -2875,-138.41 -2875,-37.5 cw(c-2825,-37.5) -2825,12.5 -2425,12.5 ; v1(-2335,-137.25) cw(c-2335,-109.75) -2362.5,-109.75 -2362.5,-50 ; -2425,12.5 cw(c-2425,-50) -2362.5,-50 ; -2425,12.5 cw(c-2425,-50) -2362.5,-50 ; -2425,12.5 cw(c-2425,-50) -2362.5,-50 ; -2425,12.5 cw(c-2425,-50) -2362.5,-50 ; -2425,12.5 cw(c-2425,-50) -2362.5,-50
  Bottom Layer w9: v1(-2335,-137.25) ccw(c-2309.15,-137.25) -2309.15,-163.09 C351K.2@-2300,-163.09 ; C351K.2@-2300,-162.5 -2299.41,-163.09 R367K.2@-2250,-163.09
ANALOG3.A2_N: C351L.1 P1.32 R351L.2 | length 1703.2
  Int5 (ST) w6: P1.32@-3427.3,-662.5 -3310.3,-662.5 ccw(c-3277.3,-662.5) -3244.3,-662.5 -2425,-662.5 ; v1(-2317.5,-767.5) -2332.5,-767.5 cw(c-2332.5,-737.5) -2362.5,-737.5 -2362.5,-725 ; -2425,-662.5 cw(c-2425,-725) -2362.5,-725 ; -2425,-662.5 cw(c-2425,-725) -2362.5,-725 ; -2425,-662.5 cw(c-2425,-725) -2362.5,-725 ; -2425,-662.5 cw(c-2425,-725) -2362.5,-725 ; -2425,-662.5 cw(c-2425,-725) -2362.5,-725
  Bottom Layer w9: v1(-2317.5,-767.5) -2300,-785 C351L.1@-2300,-786.91 -2250.59,-737.5 R351L.2@-2249.41,-737.5
ANALOG3.A2_P: C351L.2 P1.31 R367L.2 | length 1546.1
  Int6 (SB) w6: P1.31@-3277.3,-662.5 -2425,-662.5 ; v1(-2335,-812.25) cw(c-2335,-784.75) -2362.5,-784.75 -2362.5,-725 ; -2425,-662.5 cw(c-2425,-725) -2362.5,-725 ; -2425,-662.5 cw(c-2425,-725) -2362.5,-725 ; -2425,-662.5 cw(c-2425,-725) -2362.5,-725 ; -2425,-662.5 cw(c-2425,-725) -2362.5,-725 ; -2425,-662.5 cw(c-2425,-725) -2362.5,-725
  Bottom Layer w9: v1(-2335,-812.25) ccw(c-2309.15,-812.25) -2309.15,-838.09 C351L.2@-2300,-838.09 ; C351L.2@-2300,-837.5 -2299.41,-838.09 R367L.2@-2250,-838.09
ANALOG3.A3_N: C431K.1 P1.42 R415K.2 | length 1067.3
  Int5 (ST) w6: P1.42@-3352.3,-412.5 -3235.3,-412.5 ccw(c-3202.3,-412.5) -3169.3,-412.5 -3129.63,-412.5 -3129.55,-412.5 ccw(c-3129.55,-313.58) -3059.58,-383.51 -2875.12,-199.04 ccw(c-2935.75,-138.41) -2850,-138.41 -2850,-37.5 cw(c-2825,-37.5) -2825,-12.5 -2787.5,-12.5 cw(c-2787.5,-37.5) -2762.5,-37.5 -2762.5,-62.5 ccw(c-2732.5,-62.5) -2732.5,-92.5 v1(-2717.5,-92.5)
  Bottom Layer w9: v1(-2717.5,-92.5) C431K.1@-2700,-111.91 R415K.2@-2649.41,-62.5
ANALOG3.A3_P: C431K.2 P1.41 R431K.2 | length 910.9
  Int6 (SB) w6: P1.41@-3202.3,-412.5 -3129.99,-412.5 ccw(c-3129.99,-312.5) -3059.28,-383.21 -2875.12,-199.04 ccw(c-2935.75,-138.41) -2850,-138.41 -2850,-37.5 cw(c-2825,-37.5) -2825,-12.5 -2787.5,-12.5 cw(c-2787.5,-37.5) -2762.5,-37.5 -2762.5,-110 ccw(c-2735,-110) v1(-2735,-137.5)
  Bottom Layer w9: v1(-2735,-137.5) ccw(c-2709.41,-137.5) -2709.41,-163.09 C431K.2@-2700,-163.09 R431K.2@-2650,-163.09
ANALOG3.A4_N: C431L.1 P1.30 R415L.2 | length 840
  Int5 (ST) w6: P1.30@-3352.3,-712.5 -3235.3,-712.5 ccw(c-3202.3,-712.5) -3169.3,-712.5 cw(c-3144.3,-712.5) -3144.3,-687.5 -2787.5,-687.5 cw(c-2787.5,-712.5) -2762.5,-712.5 -2762.5,-737.5 ccw(c-2732.5,-737.5) -2732.5,-767.5 v1(-2717.5,-767.5)
  Bottom Layer w9: v1(-2717.5,-767.5) C431L.1@-2700,-786.91 R415L.2@-2649.41,-737.5
ANALOG3.A4_P: C431L.2 P1.29 R431L.2 | length 676.1
  Int6 (SB) w6: P1.29@-3202.3,-712.5 cw(c-3141.95,-772.86) -3141.95,-687.5 -2883.58,-687.5 -2787.5,-687.5 cw(c-2787.5,-712.5) -2762.5,-712.5 -2762.5,-785 ccw(c-2735,-785) v1(-2735,-812.5)
  Bottom Layer w9: v1(-2735,-812.5) ccw(c-2709.41,-812.5) -2709.41,-838.09 C431L.2@-2700,-838.09 R431L.2@-2650,-838.09
ANALOG3.A5_N: C351J.1 P1.40 R351J.2 | length 1800.1
  Int5 (ST) w6: P1.40@-3427.3,-462.5 -3310.3,-462.5 ccw(c-3277.3,-462.5) -3244.3,-462.5 -3139.34,-462.5 ccw(c-3139.34,-362.5) -3068.63,-433.21 -2864.12,-228.7 cw(c-2825,-267.83) -2825,-212.5 -2425,-212.5 ; v1(-2317.5,-317.5) -2332.5,-317.5 cw(c-2332.5,-287.5) -2362.5,-287.5 -2362.5,-275 ; -2425,-212.5 cw(c-2425,-275) -2362.5,-275 ; -2425,-212.5 cw(c-2425,-275) -2362.5,-275 ; -2425,-212.5 cw(c-2425,-275) -2362.5,-275 ; -2425,-212.5 cw(c-2425,-275) -2362.5,-275 ; -2425,-212.5 cw(c-2425,-275) -2362.5,-275
  Bottom Layer w9: v1(-2317.5,-317.5) -2300,-335 C351J.1@-2300,-336.91 -2250.59,-287.5 R351J.2@-2249.41,-287.5
ANALOG3.A5_P: C351J.2 P1.39 R367J.2 | length 1643
  Int6 (SB) w6: P1.39@-3277.3,-462.5 -3139.34,-462.5 ccw(c-3139.34,-362.5) -3068.63,-433.21 -2864.12,-228.7 cw(c-2825,-267.83) -2825,-212.5 -2425,-212.5 ; v1(-2335,-362.25) cw(c-2335,-334.75) -2362.5,-334.75 -2362.5,-275 ; -2425,-212.5 cw(c-2425,-275) -2362.5,-275 ; -2425,-212.5 cw(c-2425,-275) -2362.5,-275 ; -2425,-212.5 cw(c-2425,-275) -2362.5,-275 ; -2425,-212.5 cw(c-2425,-275) -2362.5,-275 ; -2425,-212.5 cw(c-2425,-275) -2362.5,-275
  Bottom Layer w9: v1(-2335,-362.25) ccw(c-2309.15,-362.25) -2309.15,-388.09 C351J.2@-2300,-388.09 ; C351J.2@-2300,-387.5 -2299.41,-388.09 R367J.2@-2250,-388.09
ANALOG3.A6_N: C351I.1 P1.36 R351I.2 | length 1785.3
  Int5 (ST) w6: P1.36@-3427.3,-562.5 -3310.3,-562.5 ccw(c-3277.3,-562.5) -3244.3,-562.5 -2925,-562.5 ccw(c-2925,-512.5) -2875,-512.5 -2875,-487.5 cw(c-2825,-487.5) -2825,-437.5 -2425,-437.5 ; v1(-2317.5,-542.5) -2332.5,-542.5 cw(c-2332.5,-512.5) -2362.5,-512.5 -2362.5,-500 ; -2425,-437.5 cw(c-2425,-500) -2362.5,-500 ; -2425,-437.5 cw(c-2425,-500) -2362.5,-500 ; -2425,-437.5 cw(c-2425,-500) -2362.5,-500 ; -2425,-437.5 cw(c-2425,-500) -2362.5,-500 ; -2425,-437.5 cw(c-2425,-500) -2362.5,-500
  Bottom Layer w9: v1(-2317.5,-542.5) -2300,-560 C351I.1@-2300,-561.91 -2250.59,-512.5 R351I.2@-2249.41,-512.5
ANALOG3.A6_P: C351I.2 P1.35 R367I.2 | length 1628.2
  Int6 (SB) w6: P1.35@-3277.3,-562.5 -2925,-562.5 ccw(c-2925,-512.62) -2875.12,-512.62 -2875.12,-487.62 cw(c-2825,-487.62) -2825,-437.5 -2425,-437.5 ; v1(-2335,-587.25) cw(c-2335,-559.75) -2362.5,-559.75 -2362.5,-500 ; -2425,-437.5 cw(c-2425,-500) -2362.5,-500 ; -2425,-437.5 cw(c-2425,-500) -2362.5,-500 ; -2425,-437.5 cw(c-2425,-500) -2362.5,-500 ; -2425,-437.5 cw(c-2425,-500) -2362.5,-500 ; -2425,-437.5 cw(c-2425,-500) -2362.5,-500
  Bottom Layer w9: v1(-2335,-587.25) ccw(c-2309.15,-587.25) -2309.15,-613.09 C351I.2@-2300,-613.09 ; C351I.2@-2300,-612.5 -2299.41,-613.09 R367I.2@-2250,-613.09
ANALOG3.A7_N: C431J.1 P1.38 R415J.2 | length 934.8
  Int5 (ST) w6: P1.38@-3352.3,-512.5 -3235.3,-512.5 ccw(c-3202.3,-512.5) -3169.3,-512.5 -3146.27,-512.5 ccw(c-3146.27,-431.12) -3088.73,-488.66 -2846.44,-246.38 cw(c-2825,-267.83) -2825,-237.5 -2787.5,-237.5 cw(c-2787.5,-262.5) -2762.5,-262.5 -2762.5,-287.5 ccw(c-2732.5,-287.5) -2732.5,-317.5 v1(-2717.5,-317.5)
  Bottom Layer w9: v1(-2717.5,-317.5) C431J.1@-2700,-336.91 R415J.2@-2649.41,-287.5
ANALOG3.A7_P: C431J.2 P1.37 R431J.2 | length 778.5
  Int6 (SB) w6: P1.37@-3202.3,-512.5 -3146.27,-512.5 ccw(c-3146.27,-431.12) -3088.73,-488.66 -2846.44,-246.38 cw(c-2825,-267.83) -2825,-237.5 -2787.5,-237.5 cw(c-2787.5,-262.5) -2762.5,-262.5 -2762.5,-335 ccw(c-2735,-335) v1(-2735,-362.5)
  Bottom Layer w9: v1(-2735,-362.5) ccw(c-2709.41,-362.5) -2709.41,-388.09 C431J.2@-2700,-388.09 R431J.2@-2650,-388.09
ANALOG3.A8_N: C431I.1 P1.34 R415I.2 | length 922.1
  Int5 (ST) w6: P1.34@-3352.3,-612.5 -3235.3,-612.5 ccw(c-3202.3,-612.5) -3169.3,-612.5 -2950,-612.5 ccw(c-2950,-512.5) -2850,-512.5 -2850,-487.5 cw(c-2825,-487.5) -2825,-462.5 -2787.5,-462.5 cw(c-2787.5,-487.5) -2762.5,-487.5 -2762.5,-512.5 ccw(c-2732.5,-512.5) -2732.5,-542.5 v1(-2717.5,-542.5)
  Bottom Layer w9: v1(-2717.5,-542.5) C431I.1@-2700,-561.91 R415I.2@-2649.41,-512.5
ANALOG3.A8_P: C431I.2 P1.33 R431I.2 | length 765.7
  Int6 (SB) w6: P1.33@-3202.3,-612.5 -2950,-612.5 ccw(c-2950,-512.5) -2850,-512.5 -2850,-487.5 cw(c-2825,-487.5) -2825,-462.5 -2787.5,-462.5 cw(c-2787.5,-487.5) -2762.5,-487.5 -2762.5,-560 ccw(c-2735,-560) v1(-2735,-587.5)
  Bottom Layer w9: v1(-2735,-587.5) ccw(c-2709.41,-587.5) -2709.41,-613.09 C431I.2@-2700,-613.09 R431I.2@-2650,-613.09
ANALOG4.A1_N: C351O.1 P1.26 R351O.2 | length 1651.3
  Int5 (ST) w6: P1.26@-3352.3,-812.5 -3235.3,-812.5 ccw(c-3202.3,-812.5) -3169.3,-812.5 -3149.63,-812.5 cw(c-3149.63,-912.5) -3078.92,-841.79 -3058.21,-862.5 ccw(c-2997.86,-802.14) -2997.86,-887.5 -2825,-887.5 -2425,-887.5 ; v1(-2317.5,-992.5) -2332.5,-992.5 cw(c-2332.5,-962.5) -2362.5,-962.5 -2362.5,-950 ; -2425,-887.5 cw(c-2425,-950) -2362.5,-950 ; -2425,-887.5 cw(c-2425,-950) -2362.5,-950 ; -2425,-887.5 cw(c-2425,-950) -2362.5,-950 ; -2425,-887.5 cw(c-2425,-950) -2362.5,-950 ; -2425,-887.5 cw(c-2425,-950) -2362.5,-950
  Bottom Layer w9: v1(-2317.5,-992.5) -2300,-1010 C351O.1@-2300,-1011.91 -2250.59,-962.5 R351O.2@-2249.41,-962.5
ANALOG4.A1_P: C351O.2 P1.25 R367O.2 | length 1494.2
  Int6 (SB) w6: P1.25@-3202.3,-812.5 -3149.63,-812.5 cw(c-3149.63,-912.5) -3078.92,-841.79 -3058.21,-862.5 ccw(c-2997.86,-802.14) -2997.86,-887.5 -2825,-887.5 -2425,-887.5 ; v1(-2335,-1037.25) cw(c-2335,-1009.75) -2362.5,-1009.75 -2362.5,-950 ; -2425,-887.5 cw(c-2425,-950) -2362.5,-950 ; -2425,-887.5 cw(c-2425,-950) -2362.5,-950 ; -2425,-887.5 cw(c-2425,-950) -2362.5,-950 ; -2425,-887.5 cw(c-2425,-950) -2362.5,-950 ; -2425,-887.5 cw(c-2425,-950) -2362.5,-950
  Bottom Layer w9: v1(-2335,-1037.25) ccw(c-2309.15,-1037.25) -2309.15,-1063.09 C351O.2@-2300,-1063.09 ; C351O.2@-2300,-1062.5 -2299.41,-1063.09 R367O.2@-2250,-1063.09
ANALOG4.A2_N: C351P.1 P1.14 R351P.2 | length 1500.4
  Int5 (ST) w6: P1.14@-3352.3,-1112.5 -3235.3,-1112.5 ccw(c-3202.3,-1112.5) -3169.3,-1112.5 cw(c-3169.3,-1189.28) -3115.01,-1134.99 -2880.98,-1369.02 cw(c-2940.68,-1428.72) -2856.25,-1428.72 -2856.25,-1531.25 ccw(c-2825,-1531.25) -2825,-1562.5 -2425,-1562.5 cw(c-2425,-1625) -2362.5,-1625 -2362.5,-1637.5 ccw(c-2332.5,-1637.5) -2332.5,-1667.5 v1(-2317.5,-1667.5)
  Bottom Layer w9: v1(-2317.5,-1667.5) -2300,-1685 C351P.1@-2300,-1686.91 -2250.59,-1637.5 R351P.2@-2249.41,-1637.5
ANALOG4.A2_P: C351P.2 P1.13 R367P.2 | length 1736
  Int6 (SB) w6: P1.13@-3202.3,-1112.5 -3169.3,-1112.5 cw(c-3169.3,-1189.28) -3115.01,-1134.99 -2880.98,-1369.02 cw(c-2940.68,-1428.72) -2856.25,-1428.72 -2856.25,-1531.25 ccw(c-2825,-1531.25) -2825,-1562.5 -2425,-1562.5 ; v1(-2335,-1712.25) cw(c-2335,-1684.75) -2362.5,-1684.75 -2362.5,-1625 ; -2425,-1562.5 cw(c-2425,-1625) -2362.5,-1625 ; -2425,-1562.5 cw(c-2425,-1625) -2362.5,-1625 ; -2425,-1562.5 cw(c-2425,-1625) -2362.5,-1625 ; -2425,-1562.5 cw(c-2425,-1625) -2362.5,-1625 ; -2425,-1562.5 cw(c-2425,-1625) -2362.5,-1625
  Bottom Layer w9: v1(-2335,-1712.25) ccw(c-2309.15,-1712.25) -2309.15,-1738.09 C351P.2@-2300,-1738.09 ; C351P.2@-2300,-1737.5 -2299.41,-1738.09 R367P.2@-2250,-1738.09
ANALOG4.A3_N: C431O.1 P1.24 R415O.2 | length 914.5
  Int5 (ST) w6: P1.24@-3427.3,-862.5 -3310.3,-862.5 ccw(c-3277.3,-862.5) -3244.3,-862.5 -3118.57,-862.5 cw(c-3118.57,-922.86) -3075.89,-880.17 -3072.86,-883.21 ccw(c-3002.14,-812.5) -3002.14,-912.5 -2825,-912.5 -2787.5,-912.5 cw(c-2787.5,-937.5) -2762.5,-937.5 -2762.5,-962.5 ccw(c-2732.5,-962.5) -2732.5,-992.5 v1(-2717.5,-992.5)
  Bottom Layer w9: v1(-2717.5,-992.5) C431O.1@-2700,-1011.91 R415O.2@-2649.41,-962.5
ANALOG4.A3_P: C431O.2 P1.23 R431O.2 | length 758.2
  Int6 (SB) w6: P1.23@-3277.3,-862.5 -3118.57,-862.5 cw(c-3118.57,-922.86) -3075.89,-880.17 -3072.86,-883.21 ccw(c-3002.14,-812.5) -3002.14,-912.5 -2825,-912.5 -2787.5,-912.5 cw(c-2787.5,-937.5) -2762.5,-937.5 -2762.5,-1010 ccw(c-2735,-1010) v1(-2735,-1037.5)
  Bottom Layer w9: v1(-2735,-1037.5) ccw(c-2709.41,-1037.5) -2709.41,-1063.09 C431O.2@-2700,-1063.09 R431O.2@-2650,-1063.09
ANALOG4.A4_N: C431P.1 P1.12 R415P.2 | length 1148.1
  Int5 (ST) w6: P1.12@-3427.3,-1162.5 -3310.3,-1162.5 ccw(c-3277.3,-1162.5) -3244.3,-1162.5 -3169.3,-1162.5 cw(c-3169.3,-1254.37) -3104.34,-1189.41 -2902.28,-1391.47 cw(c-2953.04,-1442.24) -2881.25,-1442.24 -2881.25,-1531.25 ccw(c-2825,-1531.25) -2825,-1587.5 -2787.5,-1587.5 cw(c-2787.5,-1612.5) -2762.5,-1612.5 -2762.5,-1637.5 ccw(c-2732.5,-1637.5) -2732.5,-1667.5 v1(-2717.5,-1667.5)
  Bottom Layer w9: v1(-2717.5,-1667.5) C431P.1@-2700,-1686.91 R415P.2@-2649.41,-1637.5
ANALOG4.A4_P: C431P.2 P1.11 R431P.2 | length 991.7
  Int6 (SB) w6: P1.11@-3277.3,-1162.5 -3169.3,-1162.5 cw(c-3169.3,-1254.37) -3104.34,-1189.41 -2902.28,-1391.47 cw(c-2953.04,-1442.24) -2881.25,-1442.24 -2881.25,-1531.25 ccw(c-2825,-1531.25) -2825,-1587.5 -2787.5,-1587.5 cw(c-2787.5,-1612.5) -2762.5,-1612.5 -2762.5,-1685 ccw(c-2735,-1685) v1(-2735,-1712.5)
  Bottom Layer w9: v1(-2735,-1712.5) ccw(c-2709.41,-1712.5) -2709.41,-1738.09 C431P.2@-2700,-1738.09 R431P.2@-2650,-1738.09
ANALOG4.A5_N: C351N.1 P1.22 R351N.2 | length 1706
  Int5 (ST) w6: P1.22@-3352.3,-912.5 -3235.3,-912.5 ccw(c-3202.3,-912.5) -3169.3,-912.5 cw(c-3169.3,-928.92) -3157.7,-917.3 -2991.79,-1083.21 ccw(c-2921.08,-1012.5) -2921.08,-1112.5 -2825,-1112.5 -2425,-1112.5 ; v1(-2317.5,-1217.5) -2332.5,-1217.5 cw(c-2332.5,-1187.5) -2362.5,-1187.5 -2362.5,-1175 ; -2425,-1112.5 cw(c-2425,-1175) -2362.5,-1175 ; -2425,-1112.5 cw(c-2425,-1175) -2362.5,-1175 ; -2425,-1112.5 cw(c-2425,-1175) -2362.5,-1175 ; -2425,-1112.5 cw(c-2425,-1175) -2362.5,-1175 ; -2425,-1112.5 cw(c-2425,-1175) -2362.5,-1175
  Bottom Layer w9: v1(-2317.5,-1217.5) -2300,-1235 C351N.1@-2300,-1236.91 -2250.59,-1187.5 R351N.2@-2249.41,-1187.5
ANALOG4.A5_P: C351N.2 P1.21 R367N.2 | length 1549
  Int6 (SB) w6: P1.21@-3202.3,-912.5 -3169.3,-912.5 cw(c-3169.3,-928.92) -3157.7,-917.3 -2991.79,-1083.21 ccw(c-2921.08,-1012.5) -2921.08,-1112.5 -2825,-1112.5 -2425,-1112.5 ; v1(-2335,-1262.25) cw(c-2335,-1234.75) -2362.5,-1234.75 -2362.5,-1175 ; -2425,-1112.5 cw(c-2425,-1175) -2362.5,-1175 ; -2425,-1112.5 cw(c-2425,-1175) -2362.5,-1175 ; -2425,-1112.5 cw(c-2425,-1175) -2362.5,-1175 ; -2425,-1112.5 cw(c-2425,-1175) -2362.5,-1175 ; -2425,-1112.5 cw(c-2425,-1175) -2362.5,-1175
  Bottom Layer w9: v1(-2335,-1262.25) ccw(c-2309.15,-1262.25) -2309.15,-1288.09 C351N.2@-2300,-1288.09 ; C351N.2@-2300,-1287.5 -2299.41,-1288.09 R367N.2@-2250,-1288.09
ANALOG4.A6_N: C351M.1 P1.18 R351M.2 | length 1366.9
  Int5 (ST) w6: P1.18@-3352.3,-1012.5 -3235.3,-1012.5 ccw(c-3202.3,-1012.5) -3169.3,-1012.5 cw(c-3169.3,-1059.1) -3136.35,-1026.15 -2838.26,-1324.24 ccw(c-2806.25,-1292.23) -2806.25,-1337.5 -2423.34,-1337.5 cw(c-2423.34,-1398.34) -2362.5,-1398.34 -2362.5,-1412.5 ccw(c-2332.5,-1412.5) -2332.5,-1442.5 v1(-2317.5,-1442.5)
  Bottom Layer w9: v1(-2317.5,-1442.5) -2300,-1460 C351M.1@-2300,-1461.91 -2250.59,-1412.5 R351M.2@-2249.41,-1412.5
ANALOG4.A6_P: C351M.2 P1.17 R367M.2 | length 1601.8
  Int6 (SB) w6: P1.17@-3202.3,-1012.5 -3169.3,-1012.5 cw(c-3169.3,-1059.1) -3136.35,-1026.15 -2838.26,-1324.24 ccw(c-2806.25,-1292.23) -2806.25,-1337.5 -2425,-1337.5 ; v1(-2335,-1487.25) cw(c-2335,-1459.75) -2362.5,-1459.75 -2362.5,-1400 ; -2425,-1337.5 cw(c-2425,-1400) -2362.5,-1400 ; -2425,-1337.5 cw(c-2425,-1400) -2362.5,-1400 ; -2425,-1337.5 cw(c-2425,-1400) -2362.5,-1400 ; -2425,-1337.5 cw(c-2425,-1400) -2362.5,-1400 ; -2425,-1337.5 cw(c-2425,-1400) -2362.5,-1400
  Bottom Layer w9: v1(-2335,-1487.25) ccw(c-2309.15,-1487.25) -2309.15,-1513.09 C351M.2@-2300,-1513.09 ; C351M.2@-2300,-1512.5 -2299.41,-1513.09 R367M.2@-2250,-1513.09
ANALOG4.A7_N: C431N.1 P1.20 R415N.2 | length 967.5
  Int5 (ST) w6: P1.20@-3427.3,-962.5 -3310.3,-962.5 ccw(c-3277.3,-962.5) -3244.3,-962.5 -3169.3,-962.5 cw(c-3169.3,-994.01) -3147.02,-971.73 -3010.54,-1108.21 ccw(c-2939.83,-1037.5) -2939.83,-1137.5 -2825,-1137.5 -2787.5,-1137.5 cw(c-2787.5,-1162.5) -2762.5,-1162.5 -2762.5,-1187.5 ccw(c-2732.5,-1187.5) -2732.5,-1217.5 v1(-2717.5,-1217.5)
  Bottom Layer w9: v1(-2717.5,-1217.5) C431N.1@-2700,-1236.91 R415N.2@-2649.41,-1187.5
ANALOG4.A7_P: C431N.2 P1.19 R431N.2 | length 811.2
  Int6 (SB) w6: P1.19@-3277.3,-962.5 -3169.3,-962.5 cw(c-3169.3,-994.01) -3147.02,-971.73 -3010.54,-1108.21 ccw(c-2939.83,-1037.5) -2939.83,-1137.5 -2825,-1137.5 -2787.5,-1137.5 cw(c-2787.5,-1162.5) -2762.5,-1162.5 -2762.5,-1235 ccw(c-2735,-1235) v1(-2735,-1262.5)
  Bottom Layer w9: v1(-2735,-1262.5) ccw(c-2709.41,-1262.5) -2709.41,-1288.09 C431N.2@-2700,-1288.09 R431N.2@-2650,-1288.09
ANALOG4.A8_N: C431M.1 P1.16 R415M.2 | length 1018.8
  Int5 (ST) w6: P1.16@-3427.3,-1062.5 -3310.3,-1062.5 ccw(c-3277.3,-1062.5) -3244.3,-1062.5 -3169.3,-1062.5 cw(c-3169.3,-1124.19) -3125.68,-1080.57 -2867.63,-1338.62 ccw(c-2809.98,-1280.97) -2809.98,-1362.5 -2787.5,-1362.5 cw(c-2787.5,-1387.5) -2762.5,-1387.5 -2762.5,-1412.5 ccw(c-2732.5,-1412.5) -2732.5,-1442.5 v1(-2717.5,-1442.5)
  Bottom Layer w9: v1(-2717.5,-1442.5) C431M.1@-2700,-1461.91 R415M.2@-2649.41,-1412.5
ANALOG4.A8_P: C431M.2 P1.15 R431M.2 | length 862.5
  Int6 (SB) w6: P1.15@-3277.3,-1062.5 -3169.3,-1062.5 cw(c-3169.3,-1124.19) -3125.68,-1080.57 -2867.63,-1338.62 ccw(c-2809.98,-1280.97) -2809.98,-1362.5 -2787.5,-1362.5 cw(c-2787.5,-1387.5) -2762.5,-1387.5 -2762.5,-1460 ccw(c-2735,-1460) v1(-2735,-1487.5)
  Bottom Layer w9: v1(-2735,-1487.5) ccw(c-2709.41,-1487.5) -2709.41,-1513.09 C431M.2@-2700,-1513.09 R431M.2@-2650,-1513.09
APWR1.SYNC_DIFF: R220.1 U45.Y3 U82.19 | length 4447.6
  Top Layer w9: U82.19@3045.25,-1140.16 v1(3068.75,-1140.16)
  Top Layer w10: v2(314.96,314.96) U45.Y3@334.65,334.65
  Int5 (ST) w5: v2(314.96,314.96) 320.73,320.73 cw(c354.33,287.12) 354.33,334.65 629.92,334.65 ccw(c629.92,508.43) 752.81,385.55 1068.71,701.45 cw(c1181.17,588.98) 1181.17,748.03 2274.92,748.03 cw(c2274.92,608.66) 2373.47,707.21 2742.3,338.38 cw(c2643.75,239.83) 2783.12,239.83 2783.12,25.8 ccw(c2883.12,25.8) 2812.41,-44.91 2946.68,-179.18 cw(c2848.13,-277.73) 2987.5,-277.73 2987.5,-920.89 ccw(c3072.86,-920.89) 3012.5,-981.25 cw(c2952.14,-1041.61) 3037.5,-1041.61 3037.5,-1067.5 ccw(c3137.5,-1067.49) 3066.79,-1138.2 v1(3068.75,-1140.16)
  Bottom Layer w10: v1(3068.75,-1140.16) cw(c3087.24,-1158.64) 3087.24,-1132.5 R220.1@3123.16,-1132.5
APWR2.SYNC_DUAL: R219.1 U45.AA1 U83.19 | length 3347.2
  Top Layer w6: v2(393.7,393.7) U45.AA1@413.39,374.02
  Top Layer w9: U83.19@3045.25,147.34 v1(3068.75,147.34)
  Int5 (ST) w5: v2(393.7,393.7) 629.92,393.7 ccw(c629.92,508.43) 711.05,427.31 1026.95,743.21 cw(c1181.17,588.98) 1181.17,807.09 2602.11,807.09 cw(c2602.11,667.72) 2700.66,766.27 3014.46,452.47 cw(c2943.75,381.76) 3043.75,381.76 3043.75,207.7 ccw(c3129.11,207.7) v1(3068.75,147.34)
  Bottom Layer w6: v1(3068.75,147.34) 3105.92,147.34 ccw(c3105.92,173.49) R219.1@3124.41,155
AVCC: C173.1 C213.1 C220.1 C231.1 C239.2 C240.2 R163.2 TP20.1 U45.D6 U45.D10 U45.E8 U45.F7 U45.F9 U71.10 U71.11 U71.12 | length 606.5
  Top Layer w10: U45.D10@59.06,-295.28 v2(78.74,-314.96) ; v2(78.74,-196.85) U45.F9@98.43,-216.54 ; v2(118.11,-236.22) U45.E8@137.8,-255.91 ; v2(157.48,-196.85) U45.F7@177.17,-216.54 ; U45.D6@216.54,-295.28 v2(236.22,-314.96)
  Top Layer w16: R163.2@1950,-600.59 ccw(c2000.3,-600.59) 2000.3,-650.89 v4(2043.75,-650.89) ; U71.12@2079.44,-676.48 v4(2043.75,-676.48) v4(2043.75,-650.89) ; U71.11@2079.44,-650.89 v4(2043.75,-650.89) ; U71.10@2079.44,-625.3 v4(2043.75,-625.3) v4(2043.75,-650.89)
  Bottom Layer w35: TP20.1@1450,-612.5 C173.1@1636.61,-612.5
AVCC1V8: C100.2 C194.1 FR7.1 R144.2 TP10.1 U64.7 | length 313.3
  Top Layer w7: C100.2@1462.5,1324.41 ccw(c1481.51,1343.42) 1481.51,1316.54 1520,1316.54 1524.26,1320.8 cw(c1571,1274.06) v1(1571,1340.16)
  Top Layer w10: v1(1571,1340.16) U64.7@1590.16,1340.16
  Bottom Layer w20: FR7.1@539.37,448.82 ccw(c559.06,448.82) FR7.1@559.06,429.13 ccw(c559.06,433.07) 562.99,433.07 v2(562.99,468.5) 562.99,491.14 ccw(c550.2,491.14) C194.1@550.2,503.94 ccw(c550.2,493.11) 539.37,493.11 v2(539.37,468.5) FR7.1@539.37,448.82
